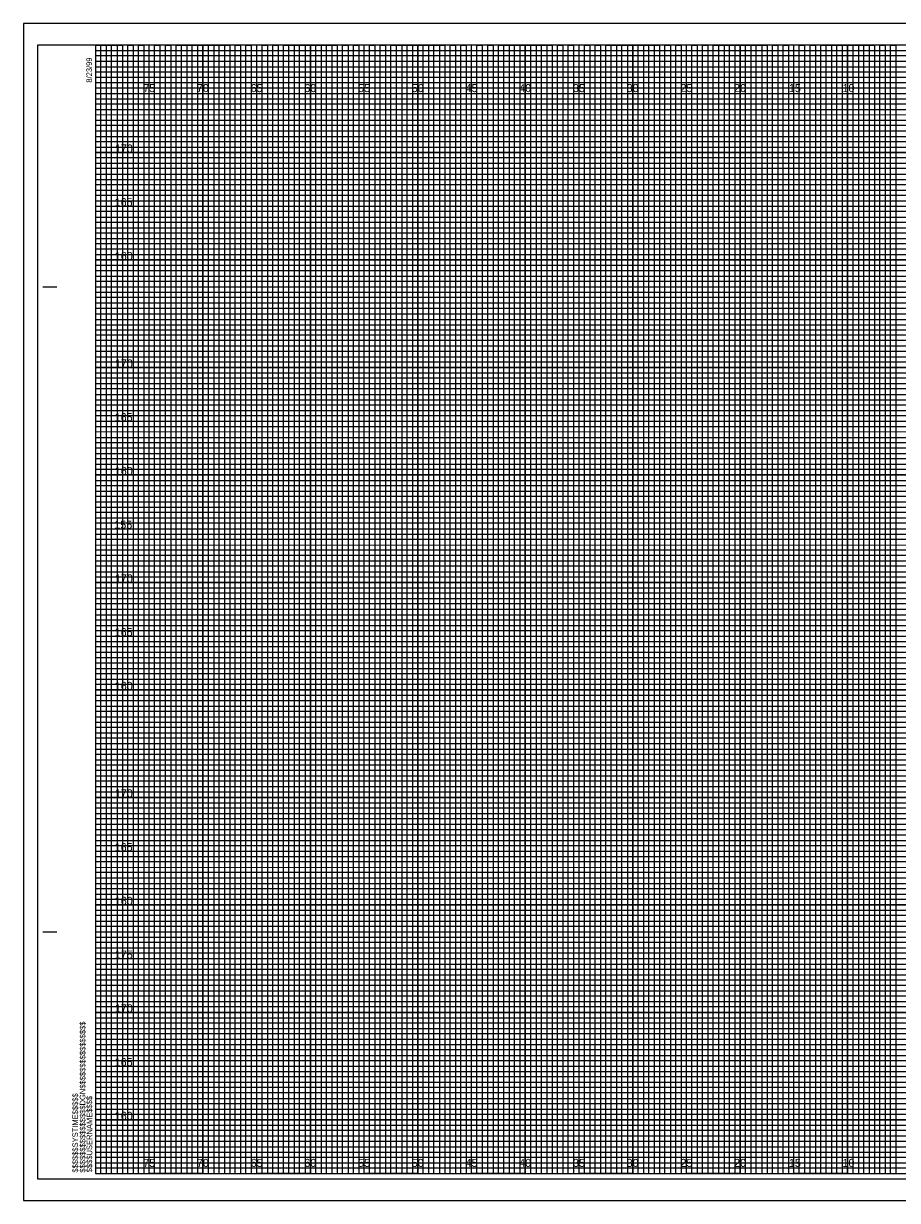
# Model space of a CAD drawing. Extents: x -7 to 162, y 878 to 987.
# Drawn here: x -6.7 to 74.6, y 877.5 to 987 of the extents above; entities that cross this region are included whole.
import ezdxf

# ---------------------------------------------------------------- set-up
doc = ezdxf.new("R2010")
doc.units = 0
for name, color, linetype in [('Prop XS Elevation Labels', 7, 'Continuous'), ('Prop XS Offset Labels', 7, 'Continuous'), ('Sheet Cross Section CELL', 7, 'Continuous'), ('Sheet Cross Section Grid Major CELL', 7, 'Continuous'), ('Sheet Cross Section Grid Middle CELL', 7, 'Continuous'), ('Sheet Cross Section Grid Minor 1 CELL', 7, 'Continuous'), ('Sheet Cross Section Grid Minor 2 CELL', 7, 'Continuous'), ('Sheet Cutting Line CELL', 7, 'Continuous'), ('Sheet DOT Grid CELL', 7, 'Continuous'), ('Sheet Plot Border Inside CELL', 7, 'Continuous'), ('Sheet Plot Border Outside CELL', 7, 'Continuous')]:
    doc.layers.add(name, color=color, linetype=linetype)

msp = doc.modelspace()

# ---------------------------------------------------------------- linework, layer by layer
at = {"layer": 'Sheet Cross Section CELL'}
for p, q in [((-4.9, 962.5), (-3.65, 962.5)), ((-4.85, 962.5), (-3.6, 962.5)), ((-4.9, 902.5), (-3.65, 902.5)), ((-4.85, 902.5), (-3.6, 902.5)), ((0, 880), (0, 880)), ((0, 880), (0, 880)), ((0, 880), (0, 880)), ((0, 880), (0, 880)), ((0, 880), (0, 880)), ((0, 880), (0, 880)), ((0, 880), (0, 880))]:
    msp.add_line(p, q, dxfattribs=at)
msp.add_lwpolyline([(160, 985), (0, 985), (0, 880), (160, 880)], close=True, dxfattribs=at)
at = {"layer": 'Sheet Cross Section Grid Major CELL'}
for p, q in [((5, 985), (0, 985)), ((5, 880), (5, 985)), ((15, 985), (10, 985)), ((10, 985), (10, 880)), ((15, 880), (15, 985)), ((25, 985), (20, 985)), ((20, 985), (20, 880)), ((25, 880), (25, 985)), ((35, 985), (30, 985)), ((30, 985), (30, 880)), ((35, 880), (35, 985)), ((45, 985), (40, 985)), ((40, 985), (40, 880)), ((45, 880), (45, 985)), ((55, 985), (50, 985)), ((50, 985), (50, 880)), ((55, 880), (55, 985)), ((65, 985), (60, 985)), ((60, 985), (60, 880)), ((65, 880), (65, 985)), ((75, 985), (70, 985)), ((70, 985), (70, 880)), ((10, 880), (5, 880)), ((20, 880), (15, 880)), ((30, 880), (25, 880)), ((40, 880), (35, 880)), ((50, 880), (45, 880)), ((60, 880), (55, 880)), ((70, 880), (65, 880))]:
    msp.add_line(p, q, dxfattribs=at)
for points in [[(0, 980), (160, 980), (160, 975), (0, 975)], [(0, 970), (160, 970), (160, 965), (0, 965)], [(0, 960), (160, 960), (160, 955), (0, 955)], [(0, 950), (160, 950), (160, 945), (0, 945)], [(0, 940), (160, 940), (160, 935), (0, 935)], [(0, 930), (160, 930), (160, 925), (0, 925)], [(0, 920), (160, 920), (160, 915), (0, 915)], [(0, 910), (160, 910), (160, 905), (0, 905)], [(0, 900), (160, 900), (160, 895), (0, 895)], [(0, 890), (160, 890), (160, 885), (0, 885)]]:
    msp.add_lwpolyline(points, dxfattribs=at)
at = {"layer": 'Sheet Cross Section Grid Middle CELL'}
for points in [[(0, 985), (2.5, 985), (2.5, 880), (7.5, 880), (7.5, 985), (12.5, 985), (12.5, 880), (17.5, 880), (17.5, 985), (22.5, 985), (22.5, 880), (27.5, 880), (27.5, 985), (32.5, 985), (32.5, 880), (37.5, 880), (37.5, 985), (42.5, 985), (42.5, 880), (47.5, 880), (47.5, 985), (52.5, 985), (52.5, 880), (57.5, 880), (57.5, 985), (62.5, 985), (62.5, 880), (67.5, 880), (67.5, 985), (72.5, 985), (72.5, 880), (77.5, 880)], [(0, 982.5), (137.5, 982.5)], [(0, 972.5), (160, 972.5), (160, 977.5), (0, 977.5)], [(0, 962.5), (160, 962.5), (160, 967.5), (0, 967.5)], [(0, 952.5), (160, 952.5), (160, 957.5), (0, 957.5)], [(0, 942.5), (160, 942.5), (160, 947.5), (0, 947.5)], [(0, 932.5), (160, 932.5), (160, 937.5), (0, 937.5)], [(0, 922.5), (160, 922.5), (160, 927.5), (0, 927.5)], [(0, 912.5), (160, 912.5), (160, 917.5), (0, 917.5)], [(0, 902.5), (160, 902.5), (160, 907.5), (0, 907.5)], [(0, 892.5), (160, 892.5), (160, 897.5), (0, 897.5)], [(0, 882.5), (160, 882.5), (160, 887.5), (0, 887.5)]]:
    msp.add_lwpolyline(points, dxfattribs=at)
at = {"layer": 'Sheet Cross Section Grid Minor 1 CELL'}
for p, q in [((0, 984.5), (130, 984.5)), ((130, 983.99), (0, 983.99)), ((0, 983.99), (0, 983.5)), ((0, 983.5), (130, 983.5)), ((130, 982.95), (0, 982.95)), ((0, 982.95), (0, 982)), ((0, 982), (160, 982))]:
    msp.add_line(p, q, dxfattribs=at)
for points in [[(0, 981.5), (135, 981.5), (160, 981.5), (160, 981), (0, 981)], [(0, 980.5), (160, 980.5), (160, 979.5), (0, 979.5)], [(0, 979), (160, 979), (160, 978.5), (0, 978.49)], [(0, 978), (160, 978), (160, 977), (0, 977)], [(0, 976.5), (160, 976.5), (160, 976), (0, 976)], [(0, 975.5), (160, 975.5), (160, 974.5), (0, 974.5)], [(0, 974), (160, 974), (160, 973.5), (0, 973.5)], [(0, 973), (160, 973), (160, 972), (0, 972)], [(0, 971.5), (160, 971.5), (160, 971), (0, 971)], [(0, 970.5), (160, 970.5), (160, 969.5), (0, 969.5)], [(0, 969), (160, 969), (160, 968.5), (0, 968.5)], [(0, 968), (160, 968), (160, 966.98), (160, 966.5), (160, 966), (0, 966)], [(0, 967), (160, 967), (160, 966.5), (0, 966.5)], [(0, 965.5), (160, 965.5), (160, 964.5), (0, 964.51)], [(0, 964.51), (160, 964.5), (160, 964), (0, 964)], [(0, 963.5), (160, 963.5), (160, 963), (0, 963)], [(0, 962), (160, 962), (160, 961.5), (0, 961.5)], [(0, 961), (160, 961), (160, 960.5), (0, 960.5)], [(-0.04, 959.45), (160, 959.45), (160, 958.94), (-0.04, 958.94)], [(0, 958.5), (160, 958.5), (160, 958), (0, 958)], [(0, 957), (160, 957), (160, 956.5), (0, 956.5)], [(0, 956), (160, 956), (160, 955.5), (0, 955.5)], [(0, 954.5), (160, 954.5), (160, 954), (0, 954)], [(0, 953.5), (160, 953.5), (160, 953), (0, 953)], [(0, 952), (160, 952), (160, 951.5), (0, 951.5)], [(0, 951), (160, 951), (160, 950.5), (0, 950.5)], [(0, 949.5), (160, 949.5), (160, 948.99), (0, 949)], [(0, 948.5), (160, 948.5), (160, 948), (0, 948)], [(0, 947), (160, 947), (160, 946.5), (0, 946.5)], [(0, 946), (160, 946), (160, 945.5), (0, 945.5)], [(0, 944.5), (160, 944.5), (160, 944), (0, 944)], [(0, 943.5), (160, 943.5), (160, 943), (0, 943)], [(0, 942), (160, 942), (160, 941.5), (0, 941.5)], [(0, 941), (160, 941), (160, 940.5), (0, 940.5)], [(0, 939.5), (160, 939.5), (160, 939), (0, 939)], [(0, 938.5), (160.03, 938.46), (160, 938), (0, 938)], [(0, 937), (160, 937), (160, 936.5), (0, 936.5)], [(0, 936), (160, 936), (160, 935.5), (0, 935.5)], [(0, 934.5), (160, 934.5), (160, 934), (0, 934)], [(0, 933.5), (160, 933.5), (160, 933), (0, 933)], [(0, 932), (160, 932), (160, 931.5), (0, 931.5)], [(0, 931), (160, 931), (160, 930.5), (0, 930.5)], [(0, 929.5), (160, 929.5), (160, 929), (0, 929)], [(0, 928.5), (160, 928.5), (160, 928), (0, 928)], [(0, 927), (160, 927), (160, 926.5), (0, 926.5)], [(0, 926), (160, 926), (160, 925.5), (0, 925.5)], [(0, 924.5), (160, 924.5), (160, 924), (0, 924)], [(0, 923.5), (160, 923.5), (160, 923), (0, 923)], [(0, 922), (160, 922), (160, 921.5), (0, 921.5)], [(0, 921), (160, 921), (160, 920.5), (0, 920.5)], [(0, 919.5), (160, 919.5), (160, 918.99), (0, 919)], [(0, 918.5), (160, 918.5), (160, 918), (0, 918)], [(0, 917), (160, 917), (160, 916.5), (0, 916.5)], [(0, 916), (160, 916), (160, 915.5), (0, 915.5)], [(0, 914.5), (160, 914.5), (160, 914), (0, 914)], [(0, 913.5), (160, 913.5), (160, 913), (0, 913)], [(0, 912), (160, 912), (160, 911.5), (0, 911.5)], [(0, 911), (160, 911), (160, 910.5), (0, 910.5)], [(0, 909.5), (160, 909.5), (160, 909), (0, 909)], [(0, 908.5), (160.03, 908.46), (160, 908), (0, 908)], [(0, 907), (160, 907), (160, 906.5), (0, 906.5)], [(0, 906), (160, 906), (160, 905.5), (0, 905.5)], [(0, 904.5), (160, 904.5), (160, 904), (0, 904)], [(0, 903.5), (160, 903.5), (160, 903), (0, 903)], [(0, 902), (160, 902), (160, 901.5), (0, 901.5)], [(0, 901), (160, 901), (160, 900.5), (0, 900.5)], [(0, 899.5), (160, 899.5), (160, 899), (0, 899)], [(0, 898.5), (160, 898.5), (160, 898), (0, 898)], [(0, 897), (160, 897), (160, 896.5), (0, 896.5)], [(0, 896), (160, 896), (160, 895.5), (0, 895.5)], [(0, 894.5), (160, 894.5), (160, 894), (0, 894)], [(0, 893.5), (160, 893.5), (160, 893), (0, 893)], [(0, 892), (160, 892), (160, 891.5), (0, 891.5)], [(0, 891), (160, 891), (160, 890.5), (0, 890.5)], [(0, 889.5), (160, 889.5), (160, 889), (0, 889)], [(0, 888.5), (160, 888.5), (160, 888), (0, 888)], [(0, 887), (160, 887), (160, 886.5), (0, 886.5)], [(0, 886), (160, 886), (160, 885.5), (0, 885.5)], [(0, 884.5), (160, 884.5), (160, 884), (0, 884)], [(0, 883.5), (160, 883.5), (160, 883), (0, 883)], [(0, 882), (160, 882), (160, 881.5), (0, 881.5)], [(0, 881), (160, 881), (160, 880.5), (0, 880.5)]]:
    msp.add_lwpolyline(points, dxfattribs=at)
at = {"layer": 'Sheet Cross Section Grid Minor 2 CELL'}
for points in [[(0, 880), (0.5, 880), (0.5, 985), (1, 985), (1, 880)], [(1, 880), (1.5, 880), (1.5, 985), (2, 985), (2, 880)], [(2.5, 880), (3, 880), (3, 985), (3.5, 985), (3.5, 880)], [(3.5, 880), (4, 880), (4, 985), (4.5, 985), (4.5, 880)], [(5, 880), (5.5, 880), (5.5, 985), (6, 985), (6, 880)], [(6, 880), (6.5, 880), (6.5, 985), (7, 985), (7, 880)], [(7.5, 880), (8, 880), (8, 985), (8.5, 985), (8.5, 880)], [(8.5, 880), (9, 880), (9, 985), (9.5, 985), (9.5, 880)], [(10, 880), (10.5, 880), (10.5, 985), (11, 985), (11, 880)], [(11, 880), (11.5, 880), (11.5, 985), (12, 985), (12, 880)], [(12.5, 880), (13, 880), (13, 985), (13.5, 985), (13.5, 880)], [(13.5, 880), (14, 880), (14, 985), (14.5, 985), (14.5, 880)], [(15, 880), (15.5, 880), (15.5, 985), (16, 985), (16, 880)], [(16, 880), (16.5, 880), (16.5, 985), (17, 985), (17, 880)], [(17.5, 880), (18, 880), (18, 985), (18.5, 985), (18.5, 880)], [(18.5, 880), (19, 880), (19, 985), (19.5, 985), (19.5, 880)], [(20, 880), (20.5, 880), (20.5, 985), (21, 985), (21, 880)], [(21, 880), (21.5, 880), (21.5, 985), (22, 985), (22, 880)], [(22.5, 880), (23, 880), (23, 985), (23.5, 985), (23.5, 880)], [(23.5, 880), (24, 880), (24, 985), (24.5, 985), (24.5, 880)], [(25, 880), (25.5, 880), (25.5, 985), (26, 985), (26, 880)], [(26, 880), (26.5, 880), (26.5, 985), (27, 985), (27, 880)], [(27.5, 880), (28, 880), (28, 985), (28.5, 985), (28.5, 880)], [(28.5, 880), (29, 880), (29, 985), (29.5, 985), (29.5, 880)], [(30, 880), (30.5, 880), (30.5, 985), (31, 985), (31, 880)], [(31, 880), (31.5, 880), (31.5, 985), (32, 985), (32, 880)], [(32.5, 880), (33, 880), (33, 985), (33.5, 985), (33.5, 880)], [(33.5, 880), (34, 880), (34, 985), (34.5, 985), (34.5, 880)], [(35, 880), (35.5, 880), (35.5, 985), (36, 985), (36, 880)], [(36, 880), (36.5, 880), (36.5, 985), (37, 985), (37, 880)], [(37.5, 880), (38, 880), (38, 985), (38.5, 985), (38.5, 880)], [(38.5, 880), (39, 880), (39, 985), (39.5, 985), (39.5, 880)], [(40, 880), (40.5, 880), (40.5, 985), (41, 985), (41, 880)], [(41, 880), (41.5, 880), (41.5, 985), (42, 985), (42, 880)], [(42.5, 880), (43, 880), (43, 985), (43.5, 985), (43.5, 880)], [(43.5, 880), (44, 880), (44, 985), (44.5, 985), (44.5, 880)], [(45, 880), (45.5, 880), (45.5, 985), (46, 985), (46, 880)], [(46, 880), (46.5, 880), (46.5, 985), (47, 985), (47, 880)], [(47.5, 880), (48, 880), (48, 985), (48.5, 985), (48.5, 880)], [(48.5, 880), (49, 880), (49, 985), (49.5, 985), (49.5, 880)], [(50, 880), (50.5, 880), (50.5, 985), (51, 985), (51, 880)], [(51, 880), (51.5, 880), (51.5, 985), (52, 985), (52, 880)], [(52.5, 880), (53, 880), (53, 985), (53.5, 985), (53.5, 880)], [(53.5, 880), (54, 880), (54, 985), (54.5, 985), (54.5, 880)], [(55, 880), (55.5, 880), (55.5, 985), (56, 985), (56, 880)], [(56, 880), (56.5, 880), (56.5, 985), (57, 985), (57, 880)], [(57.5, 880), (58, 880), (58, 985), (58.5, 985), (58.5, 880)], [(58.5, 880), (59, 880), (59, 985), (59.5, 985), (59.5, 880)], [(60, 880), (60.5, 880), (60.5, 985), (61, 985), (61, 880)], [(61, 880), (61.5, 880), (61.5, 985), (62, 985), (62, 880)], [(62.5, 880), (63, 880), (63, 985), (63.5, 985), (63.5, 880)], [(63.5, 880), (64, 880), (64, 985), (64.5, 985), (64.5, 880)], [(65, 880), (65.5, 880), (65.5, 985), (66, 985), (66, 880)], [(66, 880), (66.5, 880), (66.5, 985), (67, 985), (67, 880)], [(67.5, 880), (68, 880), (68, 985), (68.5, 985), (68.5, 880)], [(68.5, 880), (69, 880), (69, 985), (69.5, 985), (69.5, 880)], [(70, 880), (70.5, 880), (70.5, 985), (71, 985), (71, 880)], [(71, 880), (71.5, 880), (71.5, 985), (72, 985), (72, 880)], [(72.5, 880), (73, 880), (73, 985), (73.5, 985), (73.5, 880)], [(73.5, 880), (74, 880), (74, 985), (74.5, 985), (74.5, 880)]]:
    msp.add_lwpolyline(points, dxfattribs=at)
at = {"layer": 'Sheet Cutting Line CELL'}
for p, q in [((161.65, 987), (-6.7, 987)), ((-6.7, 987), (-6.7, 877.5)), ((-6.7, 877.5), (161.65, 877.5))]:
    msp.add_line(p, q, dxfattribs=at)
at = {"layer": 'Sheet DOT Grid CELL'}
for p, q in [((5, 880), (5, 985)), ((10, 880), (10, 985)), ((15, 880), (15, 985)), ((20, 880), (20, 985)), ((25, 880), (25, 985)), ((30, 880), (30, 985)), ((35, 880), (35, 985)), ((40, 880), (40, 985)), ((45, 880), (45, 985)), ((50, 880), (50, 985)), ((55, 880), (55, 985)), ((60, 880), (60, 985)), ((65, 880), (65, 985)), ((70, 880), (70, 985)), ((0, 980), (160, 980)), ((0, 975), (160, 975)), ((0, 970), (160, 970)), ((0, 965), (160, 965)), ((0, 960), (160, 960)), ((0, 955), (160, 955)), ((0, 950), (160, 950)), ((0, 945), (160, 945)), ((0, 940), (160, 940)), ((0, 935), (160, 935)), ((0, 930), (160, 930)), ((0, 925), (160, 925)), ((0, 920), (160, 920)), ((0, 915), (160, 915)), ((0, 910), (160, 910)), ((0, 905), (160, 905)), ((0, 900), (160, 900)), ((0, 895), (160, 895)), ((0, 890), (160, 890)), ((0, 885), (160, 885))]:
    msp.add_line(p, q, dxfattribs=at)
at = {"layer": 'Sheet Plot Border Inside CELL'}
msp.add_lwpolyline([(-5.4, 879.5), (161.2, 879.5), (161.2, 985), (-5.4, 985)], close=True, dxfattribs=at)
at = {"layer": 'Sheet Plot Border Outside CELL'}
msp.add_lwpolyline([(-6.7, 877.5), (161.65, 877.5), (161.65, 987), (-6.7, 987)], close=True, dxfattribs=at)

# ---------------------------------------------------------------- texts
at = {"layer": 'Prop XS Elevation Labels'}
for s, p in [('170', (1.8, 975)), ('165', (1.78, 970)), ('160', (1.79, 965)), ('170', (1.8, 955)), ('165', (1.78, 950)), ('160', (1.79, 945)), ('155', (1.75, 940)), ('170', (1.8, 935)), ('165', (1.78, 930)), ('160', (1.79, 925)), ('170', (1.8, 915)), ('165', (1.78, 910)), ('160', (1.79, 905)), ('175', (1.79, 900)), ('170', (1.8, 895)), ('165', (1.78, 890)), ('160', (1.79, 885))]:
    msp.add_text(s, height=0.75, dxfattribs=at).set_placement(p)
at = {"layer": 'Prop XS Offset Labels'}
for s, p in [('75', (4.44, 980.62)), ('70', (9.43, 980.62)), ('65', (14.44, 980.62)), ('60', (19.43, 980.62)), ('55', (24.44, 980.62)), ('50', (29.43, 980.62)), ('45', (34.44, 980.62)), ('40', (39.43, 980.62)), ('35', (44.44, 980.62)), ('30', (49.43, 980.62)), ('25', (54.44, 980.62)), ('20', (59.43, 980.62)), ('15', (64.53, 980.62)), ('10', (69.52, 980.62)), ('75', (4.44, 880.62)), ('70', (9.43, 880.62)), ('65', (14.44, 880.62)), ('60', (19.43, 880.62)), ('55', (24.44, 880.62)), ('50', (29.43, 880.62)), ('45', (34.44, 880.62)), ('40', (39.43, 880.62)), ('35', (44.44, 880.62)), ('30', (49.43, 880.62)), ('25', (54.44, 880.62)), ('20', (59.43, 880.62)), ('15', (64.53, 880.62)), ('10', (69.52, 880.62))]:
    msp.add_text(s, height=0.75, dxfattribs=at).set_placement(p)
at = {"layer": 'Sheet Cross Section CELL'}
for s, p in [('8/23/99', (-0.33, 981.5)), ('$$$$$$$$$$$$$$$$DGN$$$$$$$$$$$$$$$$', (-0.94, 880.09)), ('$$$$$$SYSTIME$$$$$', (-1.63, 880.09)), ('$$$$USERNAME$$$$', (-0.31, 880.12))]:
    msp.add_text(s, height=0.525, rotation=90, dxfattribs=at).set_placement(p)

doc.saveas('drawing.dxf')
